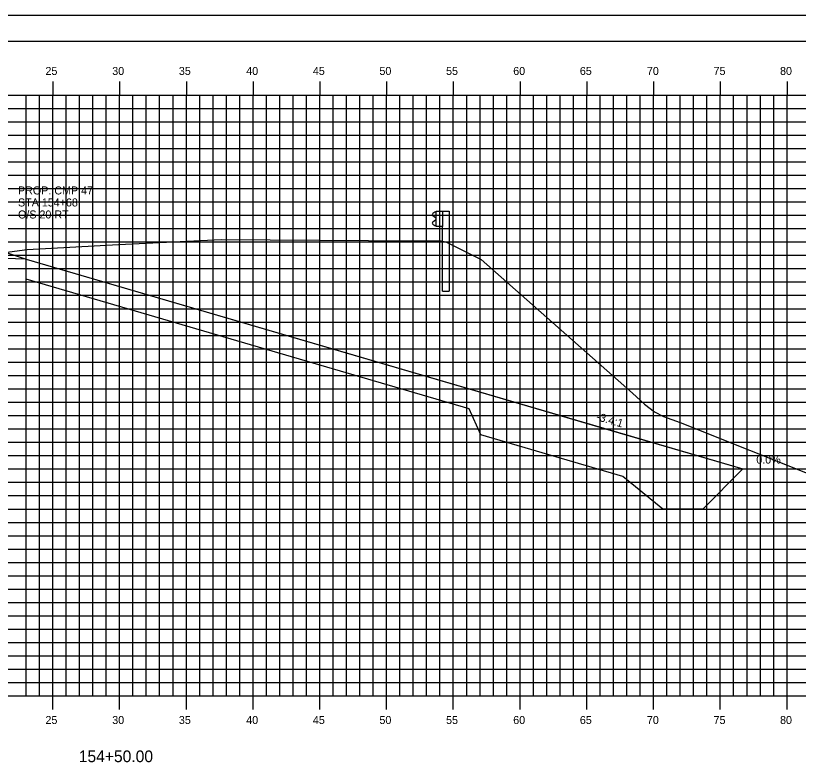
# Model space of a CAD drawing. Extents: x 850598 to 870284, y 366541 to 366651.
# Drawn here: x 852225.4 to 852284, y 366595.1 to 366651.2 of the extents above; entities that cross this region are included whole.
import ezdxf

# ---------------------------------------------------------------- set-up
doc = ezdxf.new("R2010")
doc.units = 0
for name, color, linetype in [('ANNOTATION', 7, 'Continuous'), ('BORDER', 7, 'Continuous'), ('D_Drainage_RipRap', 7, 'Continuous'), ('D_Roadway_Centerline', 7, 'Continuous'), ('D_Roadway_SlopeLines', 7, 'Continuous'), ('D_Roadway_SubGrade', 7, 'Continuous'), ('H_V ANNOTATION', 7, 'Continuous'), ('MAJOR', 7, 'Continuous'), ('MINOR', 7, 'Continuous'), ('PLOT BOUNDARY', 7, 'Continuous'), ('S_Guardrail_Beam', 7, 'Continuous'), ('S_Roadway_Centerline', 7, 'Continuous'), ('S_Utilities_Pole_Joint', 7, 'Continuous')]:
    doc.layers.add(name, color=color, linetype=linetype)

msp = doc.modelspace()

# ---------------------------------------------------------------- linework, layer by layer
at = {"layer": 'BORDER'}
msp.add_line((852318.193, 366649.225), (852158.193, 366649.225), dxfattribs=at)
at = {"layer": 'D_Drainage_RipRap'}
msp.add_lwpolyline([(852259.379, 366623.225), (852270.022, 366620.111), (852279.884, 366617.225), (852276.884, 366614.225), (852273.884, 366614.225), (852270.884, 366616.661), (852260.241, 366619.775), (852259.379, 366621.725), (852226.193, 366631.436), (852226.193, 366632.936)], close=True, dxfattribs=at)
at = {"layer": 'D_Roadway_Centerline'}
msp.add_lwpolyline([(852172.715, 366629.897), (852178.193, 366631.723), (852181.995, 366632.99), (852188.193, 366635.056), (852192.193, 366635.296), (852203.193, 366635.626), (852214.193, 366635.296), (852218.193, 366635.056), (852220.193, 366634.936), (852226.193, 366632.936), (852259.379, 366623.225), (852270.022, 366620.111), (852279.884, 366617.225), (852283.884, 366617.225)], dxfattribs=at)
at = {"layer": 'D_Roadway_SlopeLines'}
msp.add_lwpolyline([(852226.193, 366632.936), (852279.884, 366617.225), (852279.884, 366617.225)], dxfattribs=at)
at = {"layer": 'D_Roadway_SubGrade'}
msp.add_lwpolyline([(852214.193, 366634.796), (852215.193, 366634.736), (852215.193, 366634.986), (852220.193, 366634.686), (852220.193, 366634.936), (852226.193, 366632.936), (852214.193, 366633.296)], close=True, dxfattribs=at)
at = {"layer": 'MAJOR'}
for p, q in [((852228.193, 366646.227), (852228.193, 366645.225)), ((852228.193, 366646.227), (852228.193, 366645.225)), ((852233.193, 366646.227), (852233.193, 366645.225)), ((852233.193, 366646.227), (852233.193, 366645.225)), ((852238.193, 366646.227), (852238.193, 366645.225)), ((852238.193, 366646.227), (852238.193, 366645.225)), ((852243.193, 366646.227), (852243.193, 366645.225)), ((852243.193, 366646.227), (852243.193, 366645.225)), ((852248.193, 366646.227), (852248.193, 366645.225)), ((852248.193, 366646.227), (852248.193, 366645.225)), ((852253.193, 366646.227), (852253.193, 366645.225)), ((852253.193, 366646.227), (852253.193, 366645.225)), ((852258.193, 366646.227), (852258.193, 366645.225)), ((852258.193, 366646.227), (852258.193, 366645.225)), ((852263.193, 366646.227), (852263.193, 366645.225)), ((852263.193, 366646.227), (852263.193, 366645.225)), ((852268.193, 366646.227), (852268.193, 366645.225)), ((852268.193, 366646.227), (852268.193, 366645.225)), ((852273.193, 366646.227), (852273.193, 366645.225)), ((852273.193, 366646.227), (852273.193, 366645.225)), ((852278.193, 366646.227), (852278.193, 366645.225)), ((852278.193, 366646.227), (852278.193, 366645.225)), ((852283.193, 366646.227), (852283.193, 366645.225)), ((852283.193, 366646.227), (852283.193, 366645.225)), ((852163.193, 366645.225), (852303.193, 366645.225)), ((852163.193, 366645.225), (852303.193, 366645.225)), ((852163.193, 366645.225), (852303.193, 366645.225)), ((852163.193, 366645.225), (852303.193, 366645.225)), ((852228.193, 366600.225), (852228.193, 366645.225)), ((852228.193, 366600.225), (852228.193, 366645.225)), ((852233.193, 366600.225), (852233.193, 366645.225)), ((852233.193, 366600.225), (852233.193, 366645.225)), ((852238.193, 366600.225), (852238.193, 366645.225)), ((852238.193, 366600.225), (852238.193, 366645.225)), ((852243.193, 366600.225), (852243.193, 366645.225)), ((852243.193, 366600.225), (852243.193, 366645.225)), ((852248.193, 366600.225), (852248.193, 366645.225)), ((852248.193, 366600.225), (852248.193, 366645.225)), ((852253.193, 366600.225), (852253.193, 366645.225)), ((852253.193, 366600.225), (852253.193, 366645.225)), ((852258.193, 366600.225), (852258.193, 366645.225)), ((852258.193, 366600.225), (852258.193, 366645.225)), ((852263.193, 366600.225), (852263.193, 366645.225)), ((852263.193, 366600.225), (852263.193, 366645.225)), ((852268.193, 366600.225), (852268.193, 366645.225)), ((852268.193, 366600.225), (852268.193, 366645.225)), ((852273.193, 366600.225), (852273.193, 366645.225)), ((852273.193, 366600.225), (852273.193, 366645.225)), ((852278.193, 366600.225), (852278.193, 366645.225)), ((852278.193, 366600.225), (852278.193, 366645.225)), ((852283.193, 366600.225), (852283.193, 366645.225)), ((852283.193, 366600.225), (852283.193, 366645.225)), ((852163.193, 366640.225), (852303.193, 366640.225)), ((852163.193, 366640.225), (852303.193, 366640.225)), ((852163.193, 366635.225), (852303.193, 366635.225)), ((852163.193, 366635.225), (852303.193, 366635.225)), ((852163.193, 366630.225), (852303.193, 366630.225)), ((852163.193, 366630.225), (852303.193, 366630.225)), ((852163.193, 366625.225), (852303.193, 366625.225)), ((852163.193, 366625.225), (852303.193, 366625.225)), ((852163.193, 366620.225), (852303.193, 366620.225)), ((852163.193, 366620.225), (852303.193, 366620.225)), ((852163.193, 366615.225), (852303.193, 366615.225)), ((852163.193, 366615.225), (852303.193, 366615.225)), ((852163.193, 366610.225), (852303.193, 366610.225)), ((852163.193, 366610.225), (852303.193, 366610.225)), ((852163.193, 366605.225), (852303.193, 366605.225)), ((852163.193, 366605.225), (852303.193, 366605.225)), ((852163.193, 366600.225), (852303.193, 366600.225)), ((852163.193, 366600.225), (852303.193, 366600.225)), ((852163.193, 366600.225), (852303.193, 366600.225)), ((852163.193, 366600.225), (852303.193, 366600.225)), ((852228.193, 366599.223), (852228.193, 366600.225)), ((852228.193, 366599.223), (852228.193, 366600.225)), ((852233.193, 366599.223), (852233.193, 366600.225)), ((852233.193, 366599.223), (852233.193, 366600.225)), ((852238.193, 366599.223), (852238.193, 366600.225)), ((852238.193, 366599.223), (852238.193, 366600.225)), ((852243.193, 366599.223), (852243.193, 366600.225)), ((852243.193, 366599.223), (852243.193, 366600.225)), ((852248.193, 366599.223), (852248.193, 366600.225)), ((852248.193, 366599.223), (852248.193, 366600.225)), ((852253.193, 366599.223), (852253.193, 366600.225)), ((852253.193, 366599.223), (852253.193, 366600.225)), ((852258.193, 366599.223), (852258.193, 366600.225)), ((852258.193, 366599.223), (852258.193, 366600.225)), ((852263.193, 366599.223), (852263.193, 366600.225)), ((852263.193, 366599.223), (852263.193, 366600.225)), ((852268.193, 366599.223), (852268.193, 366600.225)), ((852268.193, 366599.223), (852268.193, 366600.225)), ((852273.193, 366599.223), (852273.193, 366600.225)), ((852273.193, 366599.223), (852273.193, 366600.225)), ((852278.193, 366599.223), (852278.193, 366600.225)), ((852278.193, 366599.223), (852278.193, 366600.225)), ((852283.193, 366599.223), (852283.193, 366600.225)), ((852283.193, 366599.223), (852283.193, 366600.225))]:
    msp.add_line(p, q, dxfattribs=at)
at = {"layer": 'MINOR'}
for p, q in [((852226.193, 366600.225), (852226.193, 366645.225)), ((852226.193, 366600.225), (852226.193, 366645.225)), ((852227.193, 366600.225), (852227.193, 366645.225)), ((852227.193, 366600.225), (852227.193, 366645.225)), ((852229.193, 366600.225), (852229.193, 366645.225)), ((852229.193, 366600.225), (852229.193, 366645.225)), ((852230.193, 366600.225), (852230.193, 366645.225)), ((852230.193, 366600.225), (852230.193, 366645.225)), ((852231.193, 366600.225), (852231.193, 366645.225)), ((852231.193, 366600.225), (852231.193, 366645.225)), ((852232.193, 366600.225), (852232.193, 366645.225)), ((852232.193, 366600.225), (852232.193, 366645.225)), ((852234.193, 366600.225), (852234.193, 366645.225)), ((852234.193, 366600.225), (852234.193, 366645.225)), ((852235.193, 366600.225), (852235.193, 366645.225)), ((852235.193, 366600.225), (852235.193, 366645.225)), ((852236.193, 366600.225), (852236.193, 366645.225)), ((852236.193, 366600.225), (852236.193, 366645.225)), ((852237.193, 366600.225), (852237.193, 366645.225)), ((852237.193, 366600.225), (852237.193, 366645.225)), ((852239.193, 366600.225), (852239.193, 366645.225)), ((852239.193, 366600.225), (852239.193, 366645.225)), ((852240.193, 366600.225), (852240.193, 366645.225)), ((852240.193, 366600.225), (852240.193, 366645.225)), ((852241.193, 366600.225), (852241.193, 366645.225)), ((852241.193, 366600.225), (852241.193, 366645.225)), ((852242.193, 366600.225), (852242.193, 366645.225)), ((852242.193, 366600.225), (852242.193, 366645.225)), ((852244.193, 366600.225), (852244.193, 366645.225)), ((852244.193, 366600.225), (852244.193, 366645.225)), ((852245.193, 366600.225), (852245.193, 366645.225)), ((852245.193, 366600.225), (852245.193, 366645.225)), ((852246.193, 366600.225), (852246.193, 366645.225)), ((852246.193, 366600.225), (852246.193, 366645.225)), ((852247.193, 366600.225), (852247.193, 366645.225)), ((852247.193, 366600.225), (852247.193, 366645.225)), ((852249.193, 366600.225), (852249.193, 366645.225)), ((852249.193, 366600.225), (852249.193, 366645.225)), ((852250.193, 366600.225), (852250.193, 366645.225)), ((852250.193, 366600.225), (852250.193, 366645.225)), ((852251.193, 366600.225), (852251.193, 366645.225)), ((852251.193, 366600.225), (852251.193, 366645.225)), ((852252.193, 366600.225), (852252.193, 366645.225)), ((852252.193, 366600.225), (852252.193, 366645.225)), ((852254.193, 366600.225), (852254.193, 366645.225)), ((852254.193, 366600.225), (852254.193, 366645.225)), ((852255.193, 366600.225), (852255.193, 366645.225)), ((852255.193, 366600.225), (852255.193, 366645.225)), ((852256.193, 366600.225), (852256.193, 366645.225)), ((852256.193, 366600.225), (852256.193, 366645.225)), ((852257.193, 366600.225), (852257.193, 366645.225)), ((852257.193, 366600.225), (852257.193, 366645.225)), ((852259.193, 366600.225), (852259.193, 366645.225)), ((852259.193, 366600.225), (852259.193, 366645.225)), ((852260.193, 366600.225), (852260.193, 366645.225)), ((852260.193, 366600.225), (852260.193, 366645.225)), ((852261.193, 366600.225), (852261.193, 366645.225)), ((852261.193, 366600.225), (852261.193, 366645.225)), ((852262.193, 366600.225), (852262.193, 366645.225)), ((852262.193, 366600.225), (852262.193, 366645.225)), ((852264.193, 366600.225), (852264.193, 366645.225)), ((852264.193, 366600.225), (852264.193, 366645.225)), ((852265.193, 366600.225), (852265.193, 366645.225)), ((852265.193, 366600.225), (852265.193, 366645.225)), ((852266.193, 366600.225), (852266.193, 366645.225)), ((852266.193, 366600.225), (852266.193, 366645.225)), ((852267.193, 366600.225), (852267.193, 366645.225)), ((852267.193, 366600.225), (852267.193, 366645.225)), ((852269.193, 366600.225), (852269.193, 366645.225)), ((852269.193, 366600.225), (852269.193, 366645.225)), ((852270.193, 366600.225), (852270.193, 366645.225)), ((852270.193, 366600.225), (852270.193, 366645.225)), ((852271.193, 366600.225), (852271.193, 366645.225)), ((852271.193, 366600.225), (852271.193, 366645.225)), ((852272.193, 366600.225), (852272.193, 366645.225)), ((852272.193, 366600.225), (852272.193, 366645.225)), ((852274.193, 366600.225), (852274.193, 366645.225)), ((852274.193, 366600.225), (852274.193, 366645.225)), ((852275.193, 366600.225), (852275.193, 366645.225)), ((852275.193, 366600.225), (852275.193, 366645.225)), ((852276.193, 366600.225), (852276.193, 366645.225)), ((852276.193, 366600.225), (852276.193, 366645.225)), ((852277.193, 366600.225), (852277.193, 366645.225)), ((852277.193, 366600.225), (852277.193, 366645.225)), ((852279.193, 366600.225), (852279.193, 366645.225)), ((852279.193, 366600.225), (852279.193, 366645.225)), ((852280.193, 366600.225), (852280.193, 366645.225)), ((852280.193, 366600.225), (852280.193, 366645.225)), ((852281.193, 366600.225), (852281.193, 366645.225)), ((852281.193, 366600.225), (852281.193, 366645.225)), ((852282.193, 366600.225), (852282.193, 366645.225)), ((852282.193, 366600.225), (852282.193, 366645.225)), ((852163.193, 366644.225), (852303.193, 366644.225)), ((852163.193, 366644.225), (852303.193, 366644.225)), ((852163.193, 366643.225), (852303.193, 366643.225)), ((852163.193, 366643.225), (852303.193, 366643.225)), ((852163.193, 366642.225), (852303.193, 366642.225)), ((852163.193, 366642.225), (852303.193, 366642.225)), ((852163.193, 366641.225), (852303.193, 366641.225)), ((852163.193, 366641.225), (852303.193, 366641.225)), ((852163.193, 366639.225), (852303.193, 366639.225)), ((852163.193, 366639.225), (852303.193, 366639.225)), ((852163.193, 366638.225), (852303.193, 366638.225)), ((852163.193, 366638.225), (852303.193, 366638.225)), ((852163.193, 366637.225), (852303.193, 366637.225)), ((852163.193, 366637.225), (852303.193, 366637.225)), ((852163.193, 366636.225), (852303.193, 366636.225)), ((852163.193, 366636.225), (852303.193, 366636.225)), ((852163.193, 366634.225), (852303.193, 366634.225)), ((852163.193, 366634.225), (852303.193, 366634.225)), ((852163.193, 366633.225), (852303.193, 366633.225)), ((852163.193, 366633.225), (852303.193, 366633.225)), ((852163.193, 366632.225), (852303.193, 366632.225)), ((852163.193, 366632.225), (852303.193, 366632.225)), ((852163.193, 366631.225), (852303.193, 366631.225)), ((852163.193, 366631.225), (852303.193, 366631.225)), ((852163.193, 366629.225), (852303.193, 366629.225)), ((852163.193, 366629.225), (852303.193, 366629.225)), ((852163.193, 366628.225), (852303.193, 366628.225)), ((852163.193, 366628.225), (852303.193, 366628.225)), ((852163.193, 366627.225), (852303.193, 366627.225)), ((852163.193, 366627.225), (852303.193, 366627.225)), ((852163.193, 366626.225), (852303.193, 366626.225)), ((852163.193, 366626.225), (852303.193, 366626.225)), ((852163.193, 366624.225), (852303.193, 366624.225)), ((852163.193, 366624.225), (852303.193, 366624.225)), ((852163.193, 366623.225), (852303.193, 366623.225)), ((852163.193, 366623.225), (852303.193, 366623.225)), ((852163.193, 366622.225), (852303.193, 366622.225)), ((852163.193, 366622.225), (852303.193, 366622.225)), ((852163.193, 366621.225), (852303.193, 366621.225)), ((852163.193, 366621.225), (852303.193, 366621.225)), ((852163.193, 366619.225), (852303.193, 366619.225)), ((852163.193, 366619.225), (852303.193, 366619.225)), ((852163.193, 366618.225), (852303.193, 366618.225)), ((852163.193, 366618.225), (852303.193, 366618.225)), ((852163.193, 366617.225), (852303.193, 366617.225)), ((852163.193, 366617.225), (852303.193, 366617.225)), ((852163.193, 366616.225), (852303.193, 366616.225)), ((852163.193, 366616.225), (852303.193, 366616.225)), ((852163.193, 366614.225), (852303.193, 366614.225)), ((852163.193, 366614.225), (852303.193, 366614.225)), ((852163.193, 366613.225), (852303.193, 366613.225)), ((852163.193, 366613.225), (852303.193, 366613.225)), ((852163.193, 366612.225), (852303.193, 366612.225)), ((852163.193, 366612.225), (852303.193, 366612.225)), ((852163.193, 366611.225), (852303.193, 366611.225)), ((852163.193, 366611.225), (852303.193, 366611.225)), ((852163.193, 366609.225), (852303.193, 366609.225)), ((852163.193, 366609.225), (852303.193, 366609.225)), ((852163.193, 366608.225), (852303.193, 366608.225)), ((852163.193, 366608.225), (852303.193, 366608.225)), ((852163.193, 366607.225), (852303.193, 366607.225)), ((852163.193, 366607.225), (852303.193, 366607.225)), ((852163.193, 366606.225), (852303.193, 366606.225)), ((852163.193, 366606.225), (852303.193, 366606.225)), ((852163.193, 366604.225), (852303.193, 366604.225)), ((852163.193, 366604.225), (852303.193, 366604.225)), ((852163.193, 366603.225), (852303.193, 366603.225)), ((852163.193, 366603.225), (852303.193, 366603.225)), ((852163.193, 366602.225), (852303.193, 366602.225)), ((852163.193, 366602.225), (852303.193, 366602.225)), ((852163.193, 366601.225), (852303.193, 366601.225)), ((852163.193, 366601.225), (852303.193, 366601.225))]:
    msp.add_line(p, q, dxfattribs=at)
at = {"layer": 'PLOT BOUNDARY'}
msp.add_lwpolyline([(852150.1, 366541.166), (852320.1, 366541.166), (852320.1, 366651.166), (852150.1, 366651.166)], close=True, dxfattribs=at)
at = {"layer": 'S_Guardrail_Beam'}
for p, q in [((852256.8, 366636.441), (852256.657, 366636.341)), ((852256.899, 366636.463), (852256.817, 366636.448)), ((852256.899, 366636.536), (852257.389, 366636.536)), ((852256.899, 366635.369), (852256.899, 366636.536)), ((852257.389, 366636.536), (852257.88, 366636.536)), ((852257.389, 366636.536), (852257.389, 366635.369)), ((852257.88, 366636.536), (852257.88, 366630.536)), ((852256.657, 366636.198), (852256.852, 366636.062)), ((852256.852, 366635.842), (852256.657, 366635.706)), ((852256.886, 366635.998), (852256.886, 366635.907)), ((852256.657, 366635.563), (852256.8, 366635.463)), ((852256.817, 366635.456), (852256.899, 366635.442)), ((852257.389, 366635.369), (852256.899, 366635.369)), ((852257.389, 366630.536), (852257.389, 366635.369)), ((852257.389, 366630.536), (852257.88, 366630.536))]:
    msp.add_line(p, q, dxfattribs=at)
for centre, major_axis, start_param, end_param in [((852256.824, 366636.407), (-0.0417, 0), 4.886922, 5.323254), ((852256.707, 366636.27), (-0.0877, 0), 5.323254, 7.243116), ((852256.807, 366635.998), (0.0789, 0), 0, 0.959931), ((852256.807, 366635.907), (0.0789, 0), 5.323254, 6.283185), ((852256.707, 366635.635), (-0.0877, 0), 5.323254, 7.243116), ((852256.824, 366635.497), (-0.0417, 0), 0.959931, 1.396263)]:
    msp.add_ellipse(centre, major_axis=major_axis, ratio=0.995501, start_param=start_param, end_param=end_param, dxfattribs=at)
at = {"layer": 'S_Roadway_Centerline'}
msp.add_lwpolyline([(852163.193, 366629.821), (852169.749, 366629.755), (852192.19, 366630.833), (852213.344, 366631.869), (852218.98, 366632.668), (852221.58, 366633.055), (852222.854, 366633.212), (852226.268, 366633.657), (852233.105, 366634.034), (852240.803, 366634.416), (852251.826, 366634.342), (852257.286, 366634.316), (852257.632, 366634.226), (852260.282, 366632.914), (852271.613, 366622.89), (852272.519, 366622.087), (852273.262, 366621.508), (852273.925, 366621.154), (852275.185, 366620.695), (852301.398, 366610.239), (852303.193, 366610.163)], dxfattribs=at)

# ---------------------------------------------------------------- texts
at = {"layer": 'ANNOTATION'}
msp.add_text('-3.4:1', height=0.6, rotation=343.68981, dxfattribs=at).set_placement((852268.848, 366620.897))
msp.add_text('0.0%', height=0.6, dxfattribs=at).set_placement((852280.889, 366617.625))
at = {"layer": 'H_V ANNOTATION'}
for s, height, p in [('25', 0.6, (852227.639, 366646.725)), ('30', 0.6, (852232.641, 366646.725)), ('35', 0.6, (852237.633, 366646.725)), ('40', 0.6, (852242.679, 366646.725)), ('45', 0.6, (852247.671, 366646.725)), ('50', 0.6, (852252.657, 366646.725)), ('55', 0.6, (852257.649, 366646.725)), ('60', 0.6, (852262.679, 366646.725)), ('65', 0.6, (852267.671, 366646.725)), ('70', 0.6, (852272.695, 366646.725)), ('75', 0.6, (852277.687, 366646.725)), ('80', 0.6, (852282.668, 366646.725)), ('25', 0.6, (852227.639, 366598.125)), ('30', 0.6, (852232.641, 366598.125)), ('35', 0.6, (852237.633, 366598.125)), ('40', 0.6, (852242.679, 366598.125)), ('45', 0.6, (852247.671, 366598.125)), ('50', 0.6, (852252.657, 366598.125)), ('55', 0.6, (852257.649, 366598.125)), ('60', 0.6, (852262.679, 366598.125)), ('65', 0.6, (852267.671, 366598.125)), ('70', 0.6, (852272.695, 366598.125)), ('75', 0.6, (852277.687, 366598.125)), ('80', 0.6, (852282.668, 366598.125)), ('154+50.00', 0.875, (852230.134, 366595.268))]:
    msp.add_text(s, height=height, dxfattribs=at).set_placement(p)
at = {"layer": 'S_Roadway_Centerline'}
for s, p in [('L', (852231.077, 366634.695)), ('C', (852240.798, 366634.416)), ('L', (852240.803, 366634.409))]:
    msp.add_text(s, height=0.0146, dxfattribs=at).set_placement(p)
at = {"layer": 'S_Utilities_Pole_Joint'}
for s, p in [('PROP. CMP 47', (852225.583, 366637.779)), ('STA 154+68', (852225.583, 366636.879)), ('O/S 20 RT', (852225.583, 366635.979))]:
    msp.add_text(s, height=0.6, dxfattribs=at).set_placement(p)

doc.saveas('drawing.dxf')
